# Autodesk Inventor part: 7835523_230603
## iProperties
Shininess: 64.0
Length Units: 11269
Angle Units: 11279
Time Units: 11290
Mass Units: 11283
Length Display Precision: 3
Angle Display Precision: 2
Compacted: True
Part Number: 7835523_230603
Document SubType Name: Modeling
Created: 2003-07
Material: Standard
Designer: Prieler
Density: 0.0
Volumn: 0.0
Area: 0.0
PropertySet Name: Model Information
Control State: 0
Master: False
Checked Out: False
Übersetzungsnorm: IGES 5.1
Dateiname: C:\Allgemein\Misc\umw_f_weitergabe\7835523_230603.igs
Vorprozessor: VISI-Series R10 Ver 0
Postprozessor: Build: 120c, Release: 6 SP2 - Date: Mon 01/13/2003
Gesendete Einheiten: MM
Unbestimmtheit: 1e-05
Author: Prieler
